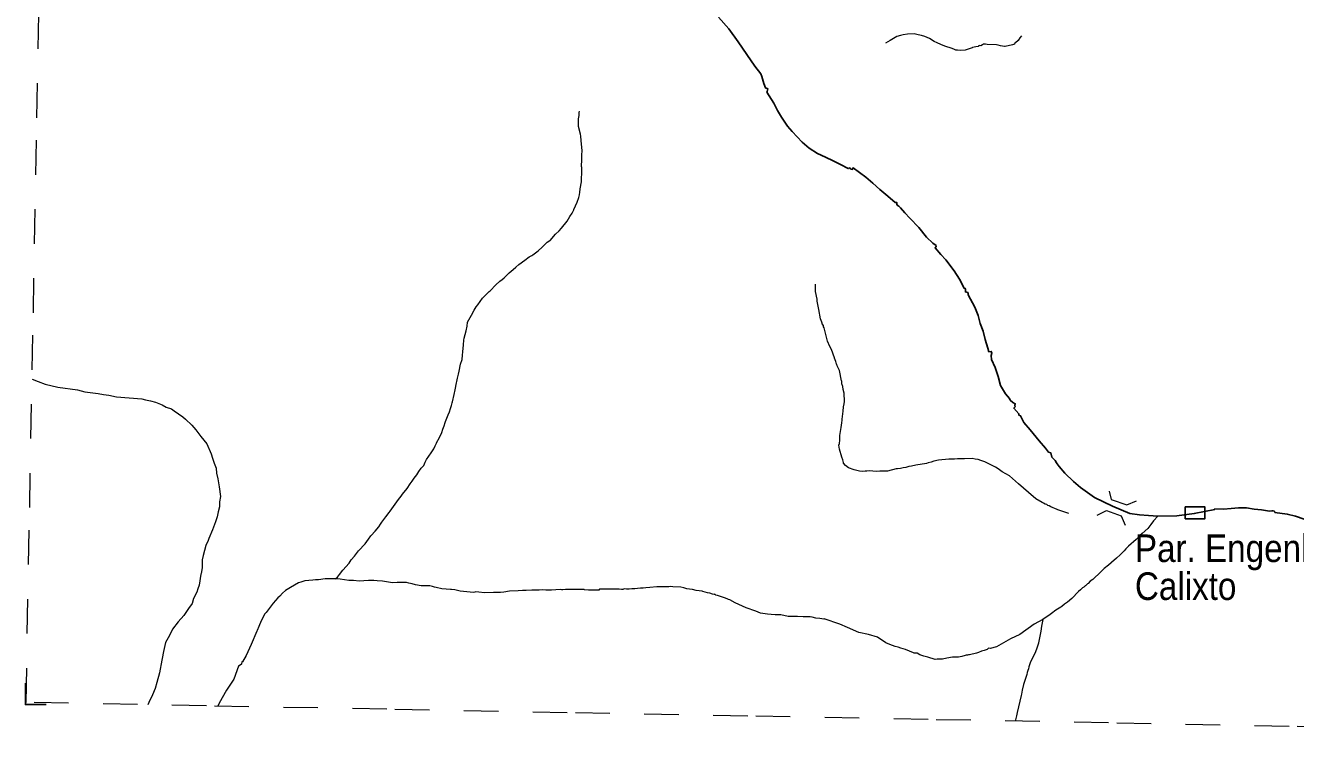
# Model space of a CAD drawing. Extents: x 781.9 to 808.1, y 7453.3 to 7481.5.
# Drawn here: x 781.91 to 785.594, y 7453.683 to 7455.766 of the extents above; entities that cross this region are included whole.
import ezdxf

# ---------------------------------------------------------------- set-up
doc = ezdxf.new("R2010")
doc.units = 0
doc.header["$LTSCALE"] = 0.032
for name, pattern in [('DOTTED', [1.5, 0.3, -1.2]), ('MEDIUM_DASHED', [4.5, 3, -1.5]), ('SHORT_DASHED', [2.7, 1.5, -1.2])]:
    doc.linetypes.add(name, pattern=pattern)
for name, color, linetype, lineweight in [('11', 7, 'Continuous', 13), ('15', 7, 'Continuous', 25), ('28', 7, 'Continuous', 25), ('35', 7, 'SHORT_DASHED', 13), ('6', 7, 'MEDIUM_DASHED', 13), ('63', 7, 'Continuous', 25), ('7', 7, 'DOTTED', 13)]:
    doc.layers.add(name, color=color, linetype=linetype, lineweight=lineweight)
doc.layers.add('61', color=7, linetype='Continuous')

msp = doc.modelspace()

# ---------------------------------------------------------------- linework, layer by layer
at = {"layer": '11'}
for points in [[(785.053, 7454.4147), (785.0592, 7454.3912), (785.1046, 7454.3756), (785.1319, 7454.3872)], [(785.0184, 7454.3456), (785.0451, 7454.3588), (785.0878, 7454.3432), (785.0993, 7454.3165)]]:
    msp.add_lwpolyline(points, dxfattribs=at)
at = {"layer": '15'}
for points in [[(783.9204, 7455.79), (783.9495, 7455.756), (783.9768, 7455.7176), (784.0024, 7455.6816), (784.0249, 7455.6472), (784.0425, 7455.6248), (784.0452, 7455.6173)], [(784.0452, 7455.6173), (784.0517, 7455.5971), (784.0558, 7455.5849), (784.0631, 7455.5816), (784.0614, 7455.5743), (784.0598, 7455.5719), (784.0801, 7455.5403), (784.0914, 7455.5192), (784.1028, 7455.4997), (784.1198, 7455.4738), (784.1336, 7455.4576), (784.1625, 7455.4272), (784.1826, 7455.4096), (784.2074, 7455.3944), (784.2301, 7455.3838), (784.2528, 7455.3725), (784.2739, 7455.3627), (784.2958, 7455.3505), (784.3006, 7455.3522), (784.3038, 7455.3489), (784.3079, 7455.3481), (784.3104, 7455.3522), (784.3468, 7455.3254), (784.3671, 7455.3084), (784.3882, 7455.2896), (784.4109, 7455.2703), (784.4328, 7455.2525), (784.4368, 7455.2525), (784.4376, 7455.2476), (784.4385, 7455.2444), (784.4433, 7455.2419), (784.4482, 7455.2363), (784.4604, 7455.2217), (784.4749, 7455.207), (784.5009, 7455.1795), (784.5236, 7455.1511), (784.5414, 7455.1341), (784.548, 7455.1292), (784.5503, 7455.1284), (784.5511, 7455.1244), (784.5479, 7455.1203), (784.5649, 7455.1017), (784.5795, 7455.0854), (784.603, 7455.0538), (784.6192, 7455.0295), (784.6323, 7455.0036), (784.6355, 7455.0028), (784.6363, 7454.9995), (784.6363, 7454.993), (784.6428, 7454.9914), (784.6444, 7454.9881), (784.6436, 7454.9841), (784.663, 7454.9484), (784.6728, 7454.9241), (784.6792, 7454.9014), (784.6874, 7454.8787), (784.6938, 7454.8544), (784.7011, 7454.8301), (784.7044, 7454.8195), (784.7108, 7454.8203), (784.7125, 7454.8147), (784.7109, 7454.8081), (784.7117, 7454.7968), (784.7222, 7454.7733), (784.7311, 7454.7474), (784.7376, 7454.7214), (784.7522, 7454.6971), (784.7635, 7454.6841), (784.766, 7454.6793), (784.7733, 7454.672), (784.7806, 7454.6687), (784.7798, 7454.6638), (784.7806, 7454.6598), (784.7765, 7454.6558), (784.7911, 7454.6395), (784.7911, 7454.6354), (784.796, 7454.633), (784.8057, 7454.6144), (784.8236, 7454.5925), (784.8503, 7454.5609), (784.8682, 7454.5398), (784.8771, 7454.5276), (784.8835, 7454.526), (784.8868, 7454.5138), (784.8965, 7454.5041), (784.9005, 7454.4968), (784.9022, 7454.4944), (784.9079, 7454.4863), (784.9241, 7454.4676), (784.9492, 7454.4433), (784.9696, 7454.4255), (784.9768, 7454.4204), (785.0105, 7454.3964), (785.0625, 7454.3716), (785.113, 7454.35)], [(785.113, 7454.35), (785.1411, 7454.346), (785.1667, 7454.3444), (785.194, 7454.342)], [(785.194, 7454.342), (785.2492, 7454.3436), (785.2997, 7454.35), (785.3598, 7454.362)], [(785.3598, 7454.362), (785.3595, 7454.3639), (785.3846, 7454.3631), (785.4073, 7454.3647), (785.4284, 7454.3663), (785.4511, 7454.3663), (785.4738, 7454.3631), (785.4949, 7454.3606), (785.5176, 7454.3574), (785.5249, 7454.3582), (785.5281, 7454.3582), (785.5321, 7454.3566), (785.5338, 7454.3533), (785.5695, 7454.3485), (785.5938, 7454.342), (785.6181, 7454.3339), (785.6424, 7454.3298), (785.6651, 7454.3258), (785.6878, 7454.3217), (785.7421, 7454.299)]]:
    msp.add_lwpolyline(points, dxfattribs=at)
at = {"layer": '28'}
msp.add_lwpolyline([(785.2739, 7454.3691), (785.3309, 7454.3691), (785.3309, 7454.3352), (785.2739, 7454.3352)], close=True, dxfattribs=at)
at = {"layer": '35'}
for points in [[(781.9116, 7453.8021), (781.9222, 7454.3673), (781.9328, 7454.9326), (781.9434, 7455.4979), (781.954, 7456.0631), (781.9646, 7456.6284), (781.9752, 7457.1936), (781.9858, 7457.7589), (781.9964, 7458.3241), (782.0069, 7458.8894), (782.0175, 7459.4547), (782.0281, 7460.0199), (782.0387, 7460.5852)], [(788.1914, 7453.6829), (787.668, 7453.6929), (787.1447, 7453.7029), (786.6214, 7453.7129), (786.0981, 7453.7229), (785.5748, 7453.7329), (785.0514, 7453.7428), (784.5281, 7453.7527), (784.0048, 7453.7626), (783.4815, 7453.7725), (782.9581, 7453.7824), (782.4349, 7453.7922), (781.9116, 7453.8021)]]:
    msp.add_lwpolyline(points, dxfattribs=at)
at = {"layer": '6'}
msp.add_lwpolyline([(781.9292, 7454.7399), (781.9467, 7454.733), (781.9667, 7454.725), (782.0035, 7454.7162), (782.0611, 7454.709), (782.0819, 7454.7034), (782.121, 7454.6978), (782.1367, 7454.6955), (782.1513, 7454.693), (782.174, 7454.689), (782.2478, 7454.6825), (782.2583, 7454.68), (782.2729, 7454.6768), (782.2875, 7454.6727), (782.3061, 7454.6654), (782.3183, 7454.6582), (782.3337, 7454.6541), (782.341, 7454.6476), (782.3661, 7454.6306), (782.3742, 7454.6233), (782.3929, 7454.6063), (782.4042, 7454.5933), (782.4188, 7454.5739), (782.4358, 7454.5519), (782.4488, 7454.5228), (782.4529, 7454.5106), (782.4577, 7454.496), (782.4626, 7454.4814), (782.4642, 7454.4669), (782.4675, 7454.4506), (782.4715, 7454.4279), (782.4756, 7454.3995), (782.4731, 7454.3842), (782.4723, 7454.3697), (782.4691, 7454.355), (782.4658, 7454.3404), (782.461, 7454.3258), (782.4521, 7454.3031), (782.4415, 7454.2779), (782.4399, 7454.2723), (782.4334, 7454.2577), (782.4293, 7454.2431), (782.4253, 7454.2285), (782.4221, 7454.2155), (782.4221, 7454.2106), (782.4221, 7454.1928), (782.4196, 7454.1766), (782.4188, 7454.1741), (782.4139, 7454.1425), (782.4099, 7454.132), (782.4066, 7454.1222), (782.3977, 7454.1036), (782.3937, 7454.089), (782.3832, 7454.0744), (782.3734, 7454.0606), (782.3694, 7454.0542), (782.3531, 7454.0363), (782.3369, 7454.0144), (782.3273, 7453.996), (782.3161, 7453.976), (782.3105, 7453.9496), (782.3069, 7453.9301), (782.3053, 7453.9244), (782.2988, 7453.888), (782.2907, 7453.8604), (782.2858, 7453.8426), (782.2786, 7453.8247), (782.2674, 7453.8023), (782.2646, 7453.7955)], dxfattribs=at)
at = {"layer": '63'}
msp.add_lwpolyline([(781.9098, 7453.8578), (781.9098, 7453.7962), (781.9705, 7453.7962)], dxfattribs=at)
at = {"layer": '7'}
for points in [[(784.7986, 7455.7356), (784.7935, 7455.7292), (784.7887, 7455.7219), (784.7814, 7455.7154), (784.7789, 7455.713), (784.7781, 7455.7114), (784.7725, 7455.7089), (784.7514, 7455.7041), (784.749, 7455.7049), (784.7376, 7455.7065), (784.7311, 7455.7081), (784.7263, 7455.7097), (784.6995, 7455.7106), (784.6939, 7455.7113), (784.689, 7455.7113), (784.6857, 7455.7097), (784.6808, 7455.7065), (784.676, 7455.7073), (784.6744, 7455.7065), (784.6744, 7455.7048), (784.6663, 7455.7032), (784.6566, 7455.7016), (784.6557, 7455.7008), (784.6355, 7455.6935), (784.6209, 7455.6927), (784.6128, 7455.6935), (784.6087, 7455.6943), (784.6063, 7455.6951), (784.6047, 7455.6959), (784.5974, 7455.6992), (784.5763, 7455.7057), (784.5649, 7455.7105), (784.5544, 7455.7154), (784.5455, 7455.7195), (784.5317, 7455.7276), (784.5187, 7455.7332), (784.509, 7455.7365), (784.4993, 7455.7381), (784.4912, 7455.7405), (784.4871, 7455.7414), (784.4685, 7455.7405), (784.4555, 7455.7381), (784.4474, 7455.7365), (784.4376, 7455.7332), (784.4368, 7455.7333), (784.4174, 7455.7219), (784.4044, 7455.7146)], [(783.4955, 7455.2209), (783.5004, 7455.2306), (783.5004, 7455.2314), (783.5101, 7455.2533), (783.515, 7455.2663), (783.5166, 7455.2744), (783.5182, 7455.2825), (783.519, 7455.2906), (783.519, 7455.2914), (783.5223, 7455.3117), (783.5231, 7455.3246), (783.5239, 7455.3344), (783.5239, 7455.3441), (783.5238, 7455.3538), (783.5231, 7455.3562), (783.5239, 7455.3765), (783.5239, 7455.3911), (783.5247, 7455.4009), (783.5247, 7455.4017), (783.5214, 7455.4317), (783.5206, 7455.4446), (783.5199, 7455.4503), (783.5142, 7455.4722), (783.5142, 7455.4852), (783.5142, 7455.4949), (783.5158, 7455.5046), (783.5157, 7455.5127), (783.5166, 7455.5168)], [(783.4315, 7455.1422), (783.4469, 7455.16), (783.4574, 7455.1698), (783.4647, 7455.1779), (783.4809, 7455.1981), (783.489, 7455.2111), (783.4955, 7455.2209)], [(782.808, 7454.1603), (782.8153, 7454.166), (782.8209, 7454.1734), (782.8307, 7454.1863), (782.8486, 7454.2066), (782.855, 7454.2155), (782.8639, 7454.2269), (782.8728, 7454.2382), (782.8761, 7454.2423), (782.8956, 7454.2625), (782.9053, 7454.2755), (782.9118, 7454.2852), (782.9126, 7454.286), (782.9239, 7454.299), (782.9345, 7454.3112), (782.9393, 7454.3193), (782.9434, 7454.325), (782.9547, 7454.3404), (782.9644, 7454.3533), (782.9677, 7454.3574), (782.9823, 7454.3768), (782.992, 7454.3906), (782.9993, 7454.4004), (783.0034, 7454.406), (783.0171, 7454.4231), (783.0253, 7454.436), (783.0317, 7454.4441), (783.0374, 7454.4522), (783.0447, 7454.462), (783.0512, 7454.4717), (783.0577, 7454.4814), (783.065, 7454.4895), (783.069, 7454.4993), (783.0731, 7454.5066), (783.0869, 7454.526), (783.0942, 7454.5382), (783.0982, 7454.5463), (783.1023, 7454.5544), (783.1023, 7454.5552), (783.1112, 7454.5706), (783.1177, 7454.5852), (783.1209, 7454.595), (783.1242, 7454.6047), (783.1274, 7454.6144), (783.1283, 7454.6168), (783.1355, 7454.6363), (783.1396, 7454.6452), (783.1428, 7454.6549), (783.1453, 7454.6631), (783.1477, 7454.6712), (783.1485, 7454.6736), (783.1534, 7454.6955), (783.1566, 7454.7085), (783.1582, 7454.7182), (783.1583, 7454.719), (783.1631, 7454.7425), (783.1663, 7454.7538), (783.168, 7454.7628), (783.172, 7454.783), (783.1769, 7454.7968), (783.1777, 7454.809), (783.1785, 7454.8187), (783.1785, 7454.8195), (783.1801, 7454.8398), (783.1817, 7454.8528), (783.1826, 7454.8584), (783.1882, 7454.8803), (783.1907, 7454.8933), (783.1923, 7454.9055), (783.2036, 7454.9257), (783.2109, 7454.9403), (783.2174, 7454.9492), (783.2215, 7454.9557), (783.2353, 7454.9744), (783.2458, 7454.9849), (783.2547, 7454.9938), (783.258, 7454.9963), (783.2742, 7455.0133), (783.2855, 7455.0238), (783.2929, 7455.0287), (783.2985, 7455.0336), (783.3131, 7455.0481), (783.3244, 7455.0579), (783.3318, 7455.0643), (783.3407, 7455.0725), (783.3585, 7455.0846), (783.3707, 7455.0943), (783.3788, 7455.0984), (783.3812, 7455.1), (783.3974, 7455.1122), (783.4088, 7455.1227), (783.4177, 7455.1308), (783.4234, 7455.1373), (783.4307, 7455.1422), (783.4315, 7455.1422)], [(784.2082, 7454.9566), (784.2065, 7454.9663), (784.2058, 7454.9719), (784.2009, 7454.9938), (784.2009, 7455.0084), (784.2009, 7455.0157)], [(784.2211, 7454.8998), (784.2203, 7454.9022), (784.2195, 7454.9054), (784.2179, 7454.9095), (784.2155, 7454.9152), (784.2106, 7454.942), (784.2082, 7454.9566)], [(784.9363, 7454.3498), (784.9046, 7454.3606), (784.9022, 7454.3615), (784.8836, 7454.3695), (784.8787, 7454.372), (784.8754, 7454.3736), (784.8722, 7454.376), (784.8674, 7454.3776), (784.8625, 7454.3801), (784.8584, 7454.3817), (784.8406, 7454.393), (784.8193, 7454.411), (784.7896, 7454.4367), (784.7725, 7454.4514), (784.7636, 7454.4595), (784.7425, 7454.4709), (784.7311, 7454.4798), (784.7238, 7454.4846), (784.7157, 7454.4887), (784.6922, 7454.5001), (784.6809, 7454.5041), (784.6728, 7454.5065), (784.6647, 7454.5082), (784.6557, 7454.5098), (784.6339, 7454.509), (784.6209, 7454.509), (784.6128, 7454.509), (784.6047, 7454.5082), (784.5966, 7454.5082), (784.5876, 7454.5074), (784.5576, 7454.5049), (784.5447, 7454.5017), (784.5366, 7454.4992), (784.5285, 7454.4968), (784.5228, 7454.4952), (784.492, 7454.4903), (784.4798, 7454.4879), (784.4717, 7454.4863), (784.4636, 7454.4838), (784.4555, 7454.4822), (784.4474, 7454.4806), (784.4393, 7454.4798), (784.4352, 7454.4798), (784.4101, 7454.4733), (784.3971, 7454.4733), (784.3874, 7454.4725), (784.3784, 7454.4717), (784.3566, 7454.4741), (784.35, 7454.4733), (784.3452, 7454.4725), (784.3371, 7454.4717), (784.329, 7454.4733), (784.3209, 7454.4749), (784.3136, 7454.4766), (784.2966, 7454.483), (784.2884, 7454.4896), (784.2828, 7454.496), (784.2828, 7454.4977), (784.2803, 7454.5058), (784.2779, 7454.5131), (784.2706, 7454.5366), (784.269, 7454.5479), (784.2706, 7454.5536), (784.2722, 7454.5625), (784.2722, 7454.5705), (784.2723, 7454.5764), (784.2755, 7454.5998), (784.2779, 7454.6128), (784.2787, 7454.6209), (784.2787, 7454.6233), (784.2811, 7454.6468), (784.2828, 7454.6598), (784.2844, 7454.6679), (784.2852, 7454.6752), (784.2844, 7454.6987), (784.282, 7454.7101), (784.2803, 7454.7182), (784.2779, 7454.7263), (784.2779, 7454.7344), (784.2771, 7454.7352), (784.2706, 7454.7652), (784.2665, 7454.7749), (784.2641, 7454.7781), (784.2633, 7454.783), (784.2625, 7454.7829), (784.2601, 7454.7912), (784.2568, 7454.8009), (784.256, 7454.8017), (784.2479, 7454.826), (784.243, 7454.8349), (784.2358, 7454.8495), (784.2266, 7454.8884), (784.2244, 7454.8916), (784.2244, 7454.8957), (784.2211, 7454.8998)], [(785.194, 7454.342), (785.1819, 7454.329), (785.1738, 7454.3185), (785.1649, 7454.3071), (785.1487, 7454.2925), (785.1422, 7454.286), (785.1316, 7454.2747), (785.109, 7454.2552), (785.1016, 7454.2479), (785.0968, 7454.2422), (785.0911, 7454.2366), (785.0846, 7454.2301), (785.0741, 7454.2204), (785.0595, 7454.2082), (785.0587, 7454.2074), (785.0506, 7454.2001), (785.0384, 7454.1903), (785.0271, 7454.179), (785.0076, 7454.1604), (785.0052, 7454.1587), (784.9979, 7454.1539), (784.9922, 7454.1474), (784.9906, 7454.1466), (784.9881, 7454.1441), (784.9841, 7454.1409), (784.9833, 7454.1401), (784.98, 7454.1368), (784.9776, 7454.136), (784.9752, 7454.1344), (784.9695, 7454.1287), (784.9638, 7454.1239), (784.9443, 7454.1036), (784.9322, 7454.0931), (784.9233, 7454.0874), (784.916, 7454.0809), (784.9128, 7454.0785), (784.8982, 7454.0695), (784.886, 7454.0606), (784.8815, 7454.0574), (784.8602, 7454.0426)], [(782.808, 7454.1603), (782.7983, 7454.1603), (782.7886, 7454.1604), (782.7796, 7454.1604), (782.7594, 7454.1579), (782.7512, 7454.1579), (782.7432, 7454.1571), (782.7318, 7454.1563), (782.7205, 7454.1547), (782.7091, 7454.1514), (782.7018, 7454.1489), (782.6783, 7454.1352), (782.6637, 7454.1271), (782.6556, 7454.119), (782.6475, 7454.1109), (782.6418, 7454.1061), (782.6288, 7454.0898), (782.6166, 7454.0744), (782.6077, 7454.0631), (782.6045, 7454.059), (782.5939, 7454.0388), (782.5866, 7454.0226), (782.5818, 7454.0112), (782.581, 7454.0088), (782.5645, 7453.9707), (782.5501, 7453.9386), (782.5393, 7453.9197), (782.5372, 7453.9196), (782.5364, 7453.9131), (782.5331, 7453.9106), (782.5283, 7453.9074), (782.5143, 7453.8701), (782.4926, 7453.838), (782.4721, 7453.7999), (782.4675, 7453.7916)], [(782.9199, 7454.1555), (782.9102, 7454.1555), (782.9045, 7454.1555), (782.8777, 7454.1538), (782.8615, 7454.1555), (782.8502, 7454.1555), (782.8477, 7454.1555), (782.8226, 7454.1596), (782.808, 7454.1603)], [(783.0147, 7454.1498), (782.9896, 7454.1498), (782.988, 7454.1498), (782.9742, 7454.149), (782.9458, 7454.1539), (782.9296, 7454.1547), (782.9199, 7454.1555)], [(784.0282, 7454.0671), (784.0005, 7454.0763), (783.9684, 7454.0908), (783.9528, 7454.1), (783.9487, 7454.1012), (783.9447, 7454.1028), (783.9374, 7454.1053), (783.9171, 7454.1125), (783.9122, 7454.1133), (783.909, 7454.1158), (783.9074, 7454.1149), (783.9025, 7454.1166), (783.8944, 7454.119), (783.888, 7454.1206), (783.8815, 7454.1222), (783.875, 7454.1239), (783.8725, 7454.1247), (783.8555, 7454.1271), (783.8442, 7454.1295), (783.8361, 7454.1312), (783.828, 7454.132), (783.8198, 7454.1344), (783.8109, 7454.1361), (783.7874, 7454.1377), (783.7817, 7454.1385), (783.7761, 7454.1376), (783.7696, 7454.1376), (783.7631, 7454.1376), (783.7566, 7454.1376), (783.7501, 7454.1377), (783.7436, 7454.1377), (783.7412, 7454.1377), (783.7209, 7454.136), (783.7096, 7454.1344), (783.7015, 7454.1336), (783.6934, 7454.1336), (783.6853, 7454.1328), (783.6772, 7454.132), (783.669, 7454.132), (783.6609, 7454.1312), (783.6528, 7454.1312), (783.6463, 7454.132), (783.6423, 7454.1295), (783.6382, 7454.1295), (783.6318, 7454.1304), (783.6253, 7454.1304), (783.6188, 7454.1312), (783.6147, 7454.1312), (783.5847, 7454.1303), (783.575, 7454.1303), (783.5725, 7454.1279), (783.5653, 7454.1279), (783.5539, 7454.128), (783.5426, 7454.1279), (783.5312, 7454.1288), (783.5304, 7454.1296), (783.5036, 7454.1296), (783.4874, 7454.1295), (783.4761, 7454.1295), (783.4688, 7454.1287), (783.4647, 7454.1288), (783.4607, 7454.1296), (783.4355, 7454.1279), (783.4193, 7454.1279), (783.4096, 7454.1287), (783.3999, 7454.1279), (783.3974, 7454.128), (783.3788, 7454.1279), (783.3626, 7454.1271), (783.3513, 7454.1271), (783.3391, 7454.1263), (783.3139, 7454.1247), (783.2977, 7454.1222), (783.288, 7454.1214), (783.2783, 7454.1215), (783.2677, 7454.1215), (783.241, 7454.1206), (783.2247, 7454.1222), (783.2166, 7454.1231), (783.2134, 7454.1223), (783.2093, 7454.1215), (783.1712, 7454.1247), (783.155, 7454.1287), (783.1453, 7454.1296), (783.1428, 7454.1296), (783.1177, 7454.132), (783.1015, 7454.1352), (783.0966, 7454.1368), (783.0902, 7454.1384), (783.0829, 7454.1401), (783.0577, 7454.1401), (783.0415, 7454.1433), (783.0318, 7454.1458), (783.0221, 7454.1482), (783.0147, 7454.1498)], [(784.1223, 7454.0517), (784.1004, 7454.0566), (784.0842, 7454.0566), (784.0728, 7454.0574), (784.0623, 7454.0582), (784.042, 7454.0614), (784.0282, 7454.0671)], [(784.8602, 7454.0426), (784.8354, 7454.0289), (784.7941, 7453.9988), (784.7668, 7453.9868), (784.7263, 7453.9639), (784.7078, 7453.9591), (784.7035, 7453.9593), (784.6987, 7453.956), (784.6906, 7453.9528), (784.6825, 7453.9505), (784.6744, 7453.9471), (784.6687, 7453.9447), (784.6484, 7453.9406), (784.6452, 7453.9406), (784.6419, 7453.9398), (784.6379, 7453.939), (784.6355, 7453.9382), (784.6257, 7453.9358), (784.616, 7453.9333), (784.6079, 7453.9333), (784.5998, 7453.9333), (784.599, 7453.9334), (784.582, 7453.9309), (784.5698, 7453.9277), (784.5625, 7453.9277), (784.5544, 7453.9277), (784.5487, 7453.9269), (784.5268, 7453.9333), (784.5155, 7453.9366), (784.5041, 7453.9407), (784.496, 7453.9447), (784.4879, 7453.9455), (784.4855, 7453.9463), (784.462, 7453.956), (784.449, 7453.9593), (784.4409, 7453.9625), (784.4328, 7453.9642), (784.432, 7453.9642), (784.4166, 7453.9698), (784.4052, 7453.9755), (784.3807, 7453.9918), (784.3554, 7453.9994), (784.3273, 7454.005), (784.294, 7454.0198), (784.2723, 7454.0295), (784.2262, 7454.0443), (784.2252, 7454.0436), (784.2139, 7454.0452), (784.2025, 7454.0468), (784.1912, 7454.0493), (784.1855, 7454.0501), (784.1652, 7454.0509), (784.149, 7454.0517), (784.1377, 7454.0517), (784.1279, 7454.0517), (784.1223, 7454.0517)], [(784.8602, 7454.0426), (784.8571, 7454.0232), (784.8547, 7454.0088), (784.8479, 7453.9747), (784.8479, 7453.9739), (784.8446, 7453.9626), (784.8381, 7453.9463), (784.8244, 7453.9196), (784.8236, 7453.9172), (784.8203, 7453.9058), (784.8187, 7453.9001), (784.817, 7453.8952), (784.817, 7453.8945), (784.8154, 7453.8888), (784.8138, 7453.8831), (784.813, 7453.8807), (784.8049, 7453.8539), (784.8008, 7453.8377), (784.7992, 7453.8263), (784.7976, 7453.8223), (784.7903, 7453.7891), (784.7862, 7453.7728), (784.7846, 7453.7631), (784.7804, 7453.748)]]:
    msp.add_lwpolyline(points, dxfattribs=at)

# ---------------------------------------------------------------- texts
at = {"layer": '61', "width": 0.9}
for s, p in [('Par. Engenheiro', (785.1277, 7454.2094)), ('Calixto', (785.1277, 7454.0995))]:
    msp.add_text(s, height=0.08, dxfattribs=at).set_placement(p)

doc.saveas('drawing.dxf')
